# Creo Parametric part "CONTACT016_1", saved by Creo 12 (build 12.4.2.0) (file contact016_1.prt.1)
Units: Custom; MM, KILOGRAM, SECS

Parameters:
  PTC_WM_ITERATION = "0"
  PTC_WM_VERSION = "-.0"
  PTC_WM_LIFECYCLE_STATE = "In Work"
  PTC_WM_LIFECYCLE = "MO_CADDocument"
  PTC_WM_CREATED_BY = "Maximilian Roepper (Z0017RMS: MO)"
  PTC_WM_CREATED_ON = "18-Sep-26 11:36:42 AM"
  PTC_WM_MODIFIED_BY = "Maximilian Roepper (Z0017RMS: MO)"
  PTC_WM_MODIFIED_ON = "18-Sep-26 11:36:46 AM"
  PDMLINKNUMBER = "PDM000071455136"
  PTC_WM_NAME = "contact016_1.prt"
  PTC_WM_NUMBER = "PDM000071455136"

Other parameters: WEIGHT, WEIGHT_FACTOR, WEIGHT_ADD, _MASS_TEMP, _DIFF_TEMP, MC_ERRORS, SUPPLIER

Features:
  1. coordinate system
  2. datum plane "PRT_YZ"
  3. datum plane "PRT_XY"
  4. datum plane "PRT_XZ"
  5. coordinate system
  6. datum axis
  7. datum axis
  8. datum axis
  9. coordinate system
  10. imported feature

Other named items: PRT, SIEMENS_MO, DRW_VIEW_ORG, PRT_X, PRT_Y, PRT_Z, CS0, ROUGH_GROB

Layers: 00_STD_CSYS-KSYS, 01_STD_PLANES-EBENEN, 02_STD_AXES-ACHSEN, 03_STD_CSYS-KSYS, 24_IMPORT_FEAT-IMPORT_KE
